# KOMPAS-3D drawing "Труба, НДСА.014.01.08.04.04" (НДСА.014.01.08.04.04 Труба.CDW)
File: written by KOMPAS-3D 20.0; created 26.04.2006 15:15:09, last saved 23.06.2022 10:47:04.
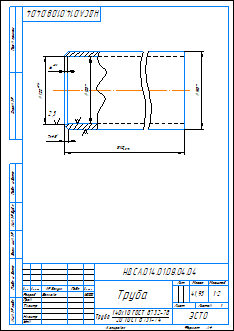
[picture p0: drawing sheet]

Sheet 1: A4, portrait

Document properties: Автор: Устинов А.В.; Организация: Эсто-вакуум; Полное имя файла: НДСА.014.01.08.04.04 Труба.m3d; 245725577220: <item xmlns="http://appius.ru/pdm" xmlns:xs="http://www.w3.org/2001/XMLSchema" xmlns:xsi="http://www.w3.org/2001/XMLSchema-instance" xsi:type="item">  <element xmlns:d2p1="http://v8.1c.ru/8.1/data/enterprise/current-config" xsi:type="d2p1:CatalogRef.aps_Элемен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; PLM_CDWXDTO: <item xmlns="http://appius.ru/pdm" xmlns:xs="http://www.w3.org/2001/XMLSchema" xmlns:xsi="http://www.w3.org/2001/XMLSchema-instance" xsi:type="item">  <element xmlns:d2p1="http://v8.1c.ru/8.1/data/enterprise/current-config" xsi:type="d2p1:CatalogRef.aps_Элемен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; Масса: 41.9469

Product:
- Part/product: Труба  | designation НДСА.014.01.08.04.04
    Материал: Труба$d140х10 ГОСТ 8732-78;20 ГОСТ 8731-74$ (density 7859 kg/m3)
    Масса: 41.9469

Title block, sheet 1: Наименование: Труба; designation: НДСА.014.01.08.04.04; Материал: Труба 140х10 ГОСТ 8732-78 20 ГОСТ 8731-74; Масса: 41,95; scale: 1:2; Количество листов документа: 1; organisation: ЭСТО; Форматы листов документа: A4; stored path: D:\WorkPDM\Устинов А.В\8b0af0dc-f3da-4f92-ad11-61854faa3fd1\УКРД.789.01.03.10.04 Труба.cdw; Разработал: Волкова; Разработал, date: 16.01.2020
Table, sheet 1:
  0;Material:V399CD8922A934364BF9D3DB1A16B3F75;Sortament:VACA86AD6B524487FA06521D22EE88F1C^SortamentEx:V3FC12F6EE58C443396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

Views: Вид 1, Спереди, Разрез А-А, Местный разрез 1
Referenced files in E:\НДСА.014.01.08.00.00 Гидроподъемник\: НДСА.014.01.08.04.04 Труба.m3d
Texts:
  НДСА.014.01.08.04.04 Труба
Dimensions and other numbers on the sheet: 120; 140; 1310; 7; 122; 6; 2,5; 1:2; 1; 41,95; 16.01.2020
